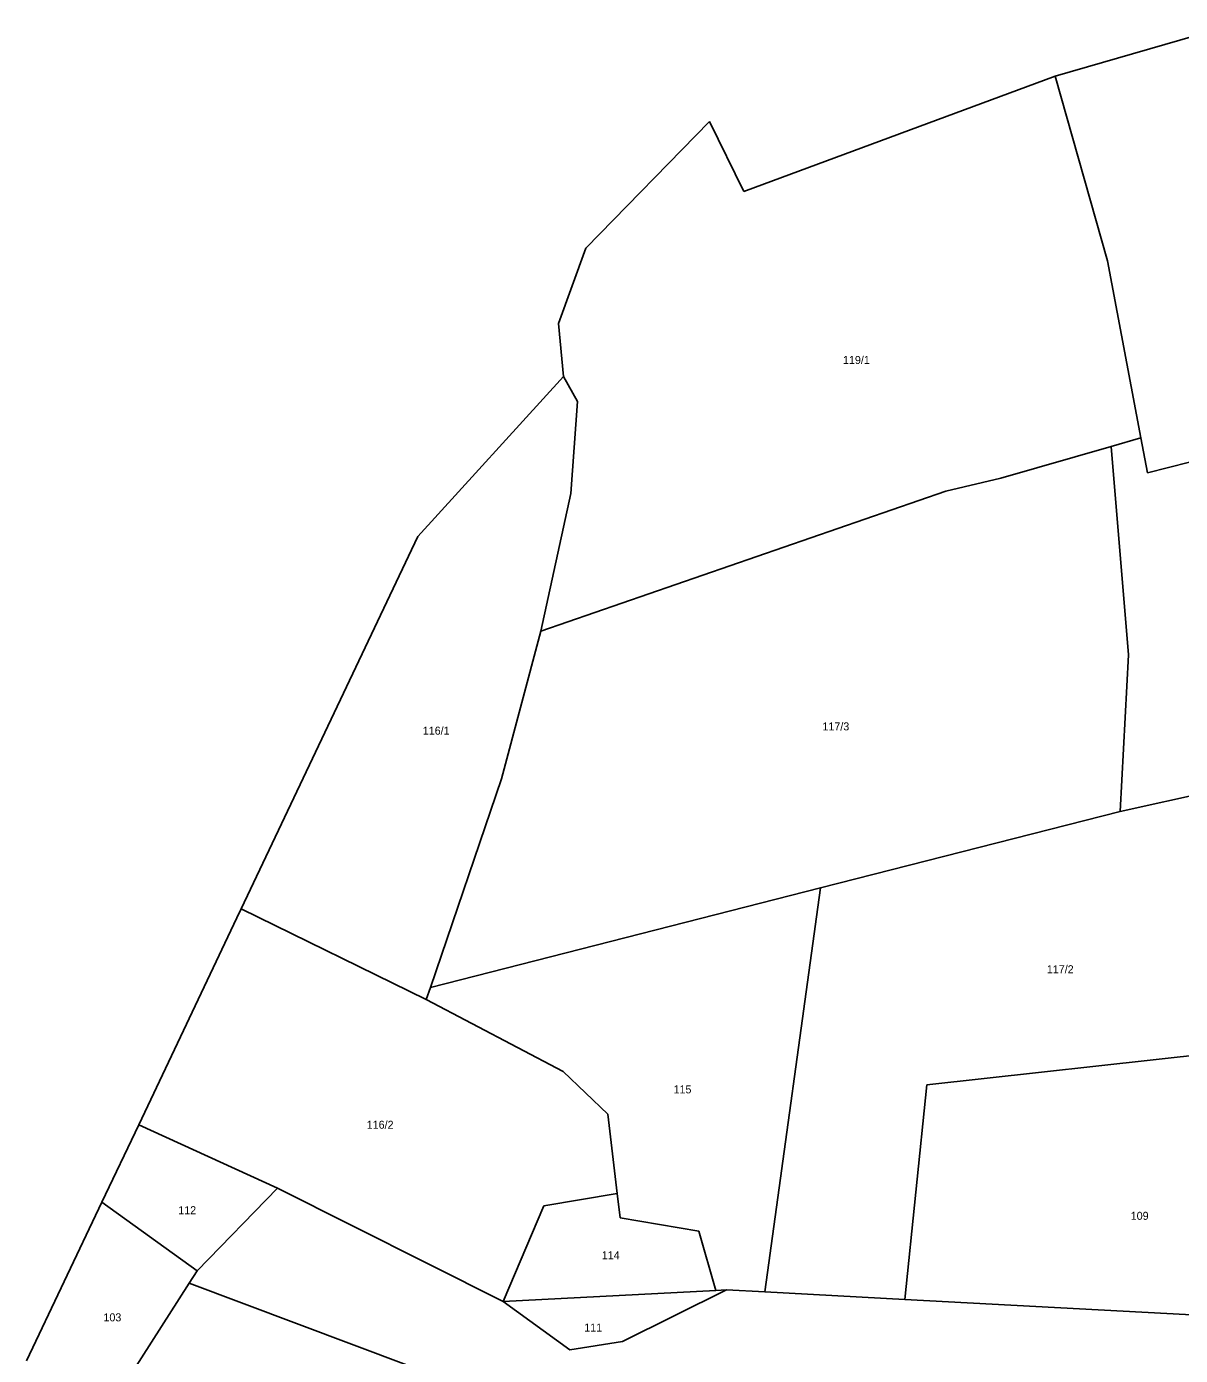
# Model space of a CAD drawing. Extents: x -664548 to -662415, y -1069720 to -1068208.
# Drawn here: x -663956.8 to -663711.8, y -1068665.4 to -1068383.2 of the extents above; entities that cross this region are included whole.
import ezdxf

# ---------------------------------------------------------------- set-up
doc = ezdxf.new("R2010")
doc.units = 0
doc.header["$LTSCALE"] = 0.68
doc.layers.add('1', color=7, linetype='Continuous', lineweight=25)
doc.layers.add('2', color=7, linetype='Continuous')

msp = doc.modelspace()

# ---------------------------------------------------------------- linework, layer by layer
at = {"layer": '1'}
for p, q in [((-663727.3, -1068432.91), (-663738.45, -1068393.73)), ((-663811.79, -1068403.34), (-663838.04, -1068430.23)), ((-663804.55, -1068418.24), (-663811.79, -1068403.34)), ((-663838.04, -1068430.23), (-663843.87, -1068446.22)), ((-663720.22, -1068470.53), (-663727.3, -1068432.91)), ((-663843.87, -1068446.22), (-663842.83, -1068457.48)), ((-663842.83, -1068457.48), (-663873.75, -1068491.5)), ((-663839.86, -1068462.83), (-663842.83, -1068457.48)), ((-663841.29, -1068482.34), (-663839.86, -1068462.83)), ((-663720.22, -1068470.53), (-663726.55, -1068472.36)), ((-663718.82, -1068477.94), (-663720.22, -1068470.53)), ((-663718.82, -1068477.94), (-663686.99, -1068469.92)), ((-663749.98, -1068479.12), (-663761.66, -1068481.87)), ((-663761.66, -1068481.87), (-663847.62, -1068511.58)), ((-663847.62, -1068511.58), (-663841.29, -1068482.34)), ((-663873.75, -1068491.5), (-663911.25, -1068570.54)), ((-663855.95, -1068542.95), (-663847.62, -1068511.58)), ((-663722.84, -1068516.62), (-663724.59, -1068549.85)), ((-663724.59, -1068549.85), (-663689.38, -1068542.03)), ((-663855.95, -1068542.95), (-663871.06, -1068587.22)), ((-663724.59, -1068549.85), (-663788.25, -1068566.09)), ((-663788.25, -1068566.09), (-663871.06, -1068587.22)), ((-663788.25, -1068566.09), (-663800.04, -1068651.9)), ((-663933.01, -1068616.4), (-663912.15, -1068572.44)), ((-663912.15, -1068572.44), (-663911.25, -1068570.54)), ((-663871.97, -1068589.77), (-663911.25, -1068570.54)), ((-663871.06, -1068587.22), (-663871.97, -1068589.77)), ((-663842.87, -1068605.1), (-663871.97, -1068589.77)), ((-663765.69, -1068607.89), (-663680.15, -1068598.53)), ((-663833.38, -1068614.12), (-663842.87, -1068605.1)), ((-663765.69, -1068607.89), (-663770.36, -1068653.5)), ((-663831.4, -1068630.99), (-663833.38, -1068614.12)), ((-663933.01, -1068616.4), (-663940.82, -1068632.85)), ((-663903.52, -1068629.85), (-663933.01, -1068616.4)), ((-663903.52, -1068629.85), (-663920.61, -1068647.42)), ((-663855.64, -1068653.91), (-663903.52, -1068629.85)), ((-663847.01, -1068633.65), (-663831.4, -1068630.99)), ((-663830.79, -1068636.14), (-663831.4, -1068630.99)), ((-663940.82, -1068632.85), (-663956.81, -1068666.54)), ((-663920.61, -1068647.42), (-663940.82, -1068632.85)), ((-663855.64, -1068653.91), (-663847.01, -1068633.65)), ((-663814.1, -1068639.01), (-663830.79, -1068636.14)), ((-663814.1, -1068639.01), (-663810.46, -1068651.57)), ((-663922.26, -1068650.01), (-663920.61, -1068647.42)), ((-663936.42, -1068672.14), (-663922.26, -1068650.01)), ((-663798.21, -1068696.66), (-663922.26, -1068650.01)), ((-663810.46, -1068651.57), (-663855.64, -1068653.91)), ((-663830.28, -1068662.39), (-663808.24, -1068651.46)), ((-663808.24, -1068651.46), (-663810.46, -1068651.57)), ((-663808.24, -1068651.46), (-663800.04, -1068651.9)), ((-663800.04, -1068651.9), (-663770.36, -1068653.5)), ((-663855.64, -1068653.91), (-663841.47, -1068664.22)), ((-663770.36, -1068653.5), (-663680.4, -1068658.35)), ((-663841.47, -1068664.22), (-663830.28, -1068662.39))]:
    msp.add_line(p, q, dxfattribs=at)
for points in [[(-663701.89, -1068383.2), (-663738.45, -1068393.73), (-663804.55, -1068418.24)], [(-663722.84, -1068516.62), (-663726.55, -1068472.36), (-663749.98, -1068479.12)]]:
    msp.add_lwpolyline(points, dxfattribs=at)

# ---------------------------------------------------------------- texts
at = {"layer": '2'}
for s, p in [('119/1', (-663783.47, -1068454.844)), ('117/3', (-663787.83, -1068532.655)), ('116/1', (-663872.69, -1068533.564)), ('117/2', (-663740.19, -1068584.225)), ('115', (-663819.45, -1068609.735)), ('116/2', (-663884.59, -1068617.245)), ('112', (-663924.6, -1068635.395)), ('109', (-663722.38, -1068636.584)), ('114', (-663834.68, -1068644.945)), ('103', (-663940.49, -1068658.145)), ('111', (-663838.41, -1068660.324))]:
    msp.add_text(s, height=1.7, dxfattribs=at).set_placement(p)

doc.saveas('drawing.dxf')
